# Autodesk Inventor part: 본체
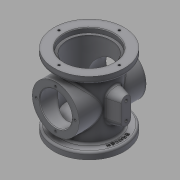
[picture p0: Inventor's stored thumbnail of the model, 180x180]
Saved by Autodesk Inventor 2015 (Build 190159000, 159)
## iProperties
Created: 2018-02
Part Number: 본체
Material: 일반
Document SubType Name: Modeling
Designer: SCD-A03
Density: 1 g/cm^3
Appearance: 기본값
Author: SCD-A03
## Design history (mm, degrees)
sketch "스케치1"
  geometry: L1 (-38, 44)-(0, 44); L2 (0, 44)-(0, -44); L3 (0, -44)-(-38, -44); L4 (-38, -44)-(-38, 44); L5 (0, 44)-(-52.5, 44); L6 (-52.5, 44)-(-52.5, 54); L7 (-52.5, 54)-(0, 54); L8 (0, 54)-(0, 44); L9 (0, -44)-(-52.5, -44); L10 (-52.5, -44)-(-52.5, -54); L11 (-52.5, -54)-(0, -54); L12 (0, -54)-(0, -44); 1 further point
  constraints: 24 end point, 6 parallel, 3 horizontal, 3 perpendicular, 1 midpoint
  dimensions: "d0" = 76 diameter of L4 L2; "d1" = 105 diameter of L6 L8; "d2" = 105 diameter of L10 L2; "d3" = 10 distance of L5.end L6.end; "d4" = 10 distance of L9.end L10.end; "d5" = 108 distance between parallel lines of L11 L7; "d6" = 54 distance from line of point (0, 0) L11
revolve "회전1" sketch "스케치1" stored, may be unused: angle "d7" = 90 deg
node "작업 평면1"
sketch "스케치2"
  geometry: C1 r 35 at (0, 0); 1 further point
  constraints: 1 centre point, 1 coincident
  dimensions: "d9" = 70 diameter of C1
extrude "돌출1" join sketch "스케치2" distance "d10" = 100; taper "d11" = 0 deg
sketch "스케치3"
  geometry: C1 r 37 at (0, 0); 1 further point
  constraints: 1 centre point, 1 coincident
  dimensions: "d12" = 74 diameter of C1
extrude "돌출2" cut sketch "스케치3" distance "d13" = 7; taper "d14" = 0 deg
sketch "스케치4"
  geometry: C1 r 33 at (0, 0); 1 further point
  constraints: 1 centre point, 1 coincident
  dimensions: "d15" = 66 diameter of C1
extrude "돌출3" cut sketch "스케치4" distance "d16" = 79; taper "d17" = 0 deg
sketch "스케치5"
  geometry: C1 r 34 at (0, 0); 1 further point
  constraints: 1 centre point, 1 coincident
  dimensions: "d18" = 68 diameter of C1
extrude "돌출4" cut sketch "스케치5" distance "d19" = 16; taper "d20" = 0 deg
hole "구멍1" diameter "d23" = 48; stored, may be unused: countersink angle "d27" = 90 deg, drill point angle "d29" = 118 deg; dims "d21" = 10, "d22" = 10, "d24" = 6, "d25" = 4, "d26" = 2, "d28" = 8
sketch "스케치6"
  geometry: C1 r 5 at (0, 0); 1 further point
  constraints: 1 centre point, 1 coincident
  dimensions: "d30" = 10 diameter of C1
extrude "돌출5" cut sketch "스케치6" stored distance "d31" = 16; taper "d32" = 0 deg
node "작업 평면2"
sketch "스케치7"
  geometry: L1 (0, 20)-(0, -20); L2 (-7, 13)-(-7, -13); L3 (7, -13)-(7, 13); A1 r 7 centre (0, 13) between (7, 13) and (-7, 13); A2 r 7 centre (0, -13) between (-7, -13) and (7, -13); 2 further points
  constraints: 8 end point, 6 point on circle, 4 tangent, 2 centre point, 2 point on line, 1 coincident, 1 midpoint, 1 parallel, 1 vertical
  dimensions: "d34" = 40 distance of L1.start L1.end; "d35" = 7 radius of A1
extrude "돌출6" join sketch "스케치7" stored distance "d36" = 16; taper "d37" = 0 deg
feature "면 기울기1" dims angle "d38" = 15 deg
sketch "스케치11" dims "d39" = 58
  geometry: L1 (0, 0)-(0, 29); 2 further points
  constraints: 2 coincident, 2 end point, 1 vertical, 1 vertical alignment, 2 other
hole "구멍2" sketch "스케치11" at (0, 29) diameter "d40" = 3.242; stored, may be unused: countersink angle "d44" = 90 deg, drill point angle "d46" = 118 deg; dims "d41" = 4, "d42" = 4, "d43" = 2, "d45" = 6
sketch "스케치12" dims "d50" = 90
  geometry: L1 (0, 0)-(0, 45); 2 further points
  constraints: 2 coincident, 2 end point, 1 vertical, 1 vertical alignment, 2 other
hole "구멍3" sketch "스케치12" at (0, 45) diameter "d51" = 3.242; stored, may be unused: countersink angle "d55" = 90 deg, drill point angle "d57" = 118 deg; dims "d52" = 4, "d53" = 4, "d54" = 2, "d56" = 6
chamfer "모따기1" distance "d61" = 1; stored, may be unused: second distance "d62" = 2, angle "d63" = 45 deg
fillet "모깎기1" dims "d64" = 3
sketch "스케치13"
  geometry: L1 (-7, 13)-(-7, -13) reference; L2 (7, -13)-(7, 13) reference; A1 r 7 centre (0, -13) between (-7, -13) and (7, -13) reference; A2 r 7 centre (0, 13) between (7, 13) and (-7, 13) reference; 3 further points
  constraints: 2 coincident
hole "구멍4" sketch "스케치13" at (0, 13), (0, -13) diameter "d65" = 4.134; stored, may be unused: countersink angle "d69" = 90 deg, drill point angle "d71" = 118 deg; dims "d66" = 6, "d67" = 4, "d68" = 2, "d70" = 8
sketch "스케치14"
  geometry: C1 r 43 at (0, 0); 1 further point
  constraints: 1 centre point, 1 coincident, 1 other
  dimensions: "d72" = 86 diameter of C1
feature "엠보싱1" sketch "스케치14" dims "d0" = 76, "d1" = 105, "d2" = 105, "d3" = 10, "d4" = 10, "d5" = 108, "d6" = 54, "d12" = 74, "d73" = 0.5, "d74" = 0
node "솔리드1"
pattern_circular "원형 패턴1" dims angle "d48" = 360 deg
mirror "대칭1"
pattern_circular "원형 패턴2" dims angle "d59" = 360 deg
node "투영된 루프1"
other parameters: "d33" = 55
